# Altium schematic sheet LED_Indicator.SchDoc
size A; SheetNumber: 5; SheetTotal: 6
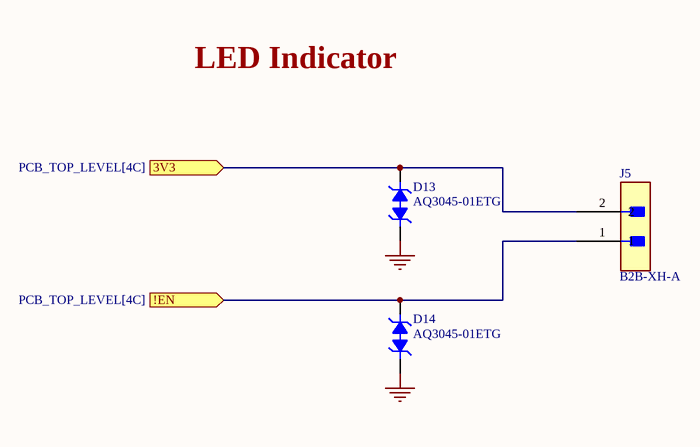
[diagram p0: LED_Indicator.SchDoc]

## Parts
D13  AQ3045-01ETG  [SOD882]
D14  AQ3045-01ETG  [SOD882]
J5  B2B-XH-A  [CONN_B2B-XH-A_JST]

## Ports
3V3 (in, see PCB_TOP_LEVEL[4C]), !EN (in, see PCB_TOP_LEVEL[4C])

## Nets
GND: D13.1 D14.1
3V3: D13.2 J5.2 ; port 3V3
!EN: D14.2 J5.1 ; port !EN

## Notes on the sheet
- LED Indicator

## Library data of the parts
D13 D14 = AQ3045-01ETG: TVS DIODE 5.3VWM 12VC SOD882; Manufacturer: Littelfuse; Diode Element Material: SILICON; Package Body Material: Plastic; Polarity: Bidirectional; Max Breakdown Voltage: 9V; Min Breakdown Voltage: 6.8V; Diode Type: TRANS VOLTAGE SUPPRESSOR; Non-rep Peak Rev Power Dis-Max: 40W; Number of Elements: 1; Rep Pk Reverse Voltage-Max: 5.3V; Reference Standard: AEC-Q101
J5 = B2B-XH-A: Board Connector, 2 Contact(s), 1 Row(s), Male, Straight, Solder Terminal; Manufacturer: JST; Contact Resistance: 20mΩ; Current Rating: 3A; Insulation Resistance: 1GΩ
